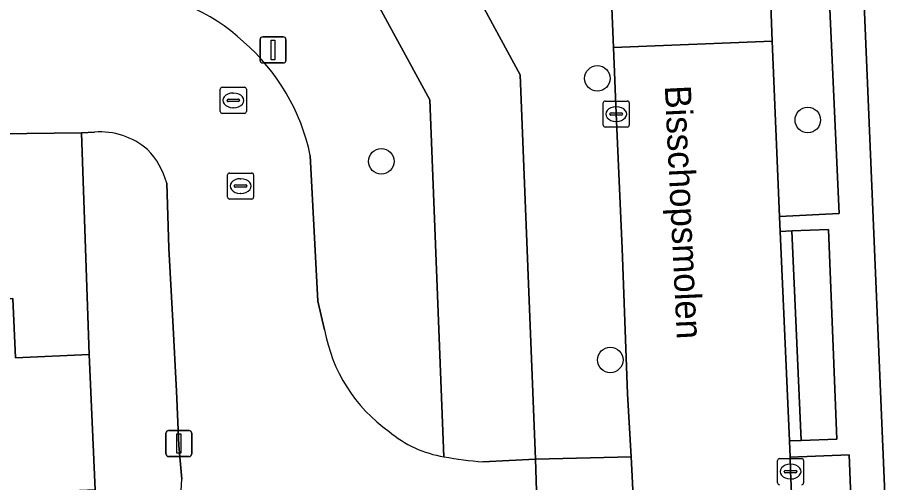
# Model space of a CAD drawing. Extents: x 161241 to 161758, y 384138 to 384885.
# Drawn here: x 161352.12 to 161385.2, y 384187.73 to 384205.58 of the extents above; entities that cross this region are included whole.
import ezdxf

# ---------------------------------------------------------------- set-up
doc = ezdxf.new("R2010")
doc.units = 0
for name, color, linetype in [('IMGEO_Boom', 7, 'Continuous'), ('IMGEO_Erf', 7, 'Continuous'), ('IMGEO_Groenvoorziening', 7, 'Continuous'), ('IMGEO_Kolk', 7, 'Continuous'), ('IMGEO_Lichtmast', 7, 'Continuous'), ('IMGEO_Openbare_ruimte_label', 7, 'Continuous'), ('IMGEO_Pand', 7, 'Continuous'), ('IMGEO_Rijbaan_lokaal_open', 7, 'Continuous'), ('IMGEO_Rioolput', 7, 'Continuous'), ('IMGEO_Voetpad_gesloten', 7, 'Continuous'), ('IMGEO_Voetpad_open', 7, 'Continuous')]:
    doc.layers.add(name, color=color, linetype=linetype)

msp = doc.modelspace()

# ---------------------------------------------------------------- linework, layer by layer
at = {"layer": 'IMGEO_Boom'}
for centre in [(161374.372, 384203.236), (161382.441, 384201.639), (161366.084, 384200.055), (161374.867, 384192.441)]:
    msp.add_circle(centre, 0.489, dxfattribs=at)
at = {"layer": 'IMGEO_Erf'}
for points in [[(161403.222, 384286.46), (161382.629, 384295.041), (161382.268, 384292.057), (161381.629, 384276.193), (161381.889, 384271.203), (161384.168, 384216.383), (161385.58, 384183.057), (161393.06, 384183.551), (161393.229, 384179.87), (161399.67, 384180.152), (161399.739, 384178.529), (161407.43, 384178.871), (161407.337, 384183.973), (161408.1, 384184.171), (161414.411, 384183.984), (161416.602, 384194.481), (161414.471, 384194.926), (161415.583, 384200.253), (161414.588, 384200.438), (161414.333, 384206.87)], [(161354.591, 384201.143), (161334.694, 384200.909), (161329.416, 384200.768), (161329.121, 384207.854), (161328.33, 384226.87), (161331.708, 384226.956), (161331.483, 384232.641), (161332.229, 384232.66), (161332.238, 384232.98), (161332.074, 384232.979), (161331.97, 384235.447), (161332.105, 384235.442), (161332.113, 384235.728), (161331.409, 384235.703), (161330.784, 384250)], [(161320.36, 384192.186), (161329.341, 384192.58), (161329.282, 384193.919), (161330.996, 384193.995), (161331.081, 384192.05), (161335.919, 384192.262), (161335.837, 384194.134), (161340.012, 384194.319), (161341.751, 384194.396), (161341.809, 384193.069), (161350.862, 384193.467), (161350.806, 384194.75), (161351.948, 384194.8), (161352.047, 384192.529), (161354.879, 384192.653), (161354.591, 384201.143)]]:
    msp.add_lwpolyline(points, dxfattribs=at)
at = {"layer": 'IMGEO_Groenvoorziening'}
for points in [[(161382.4, 384217.089), (161381.026, 384217.028), (161380.576, 384217.009), (161380.876, 384209.619), (161380.967, 384207.431), (161381.081, 384204.664), (161381.36, 384197.944), (161383.651, 384198.05), (161382.773, 384217.109)], [(161381.763, 384188.721), (161381.764, 384188.689), (161381.781, 384188.161), (161381.942, 384184.532), (161384.192, 384184.618), (161384.031, 384188.808)]]:
    msp.add_lwpolyline(points, close=True, dxfattribs=at)
for points in [[(161369.982, 384188.536), (161371.994, 384188.635), (161371.416, 384203.375), (161369.294, 384207.268), (161367.785, 384207.214), (161365.393, 384207.112), (161367.951, 384202.419), (161368.488, 384188.73)], [(161368.488, 384188.73), (161367.951, 384202.419), (161365.393, 384207.112), (161359.441, 384206.859), (161352.693, 384206.382), (161354.382, 384206.439), (161356.182, 384206.499)], [(161355.082, 384201.175), (161354.591, 384201.143), (161354.879, 384192.653), (161355.107, 384187.458), (161354.21, 384187.419), (161354.395, 384183.249)], [(161363.359, 384200.278), (161363.655, 384194.693), (161363.909, 384193.599)], [(161358.432, 384187.872), (161358.312, 384189.164), (161358.233, 384191.246), (161358.094, 384193.928), (161357.935, 384196.731), (161357.852, 384199.222)]]:
    msp.add_lwpolyline(points, dxfattribs=at)
for centre, radius, start, end in [((161356.158, 384199.791), 6.709, 46.2683, 89.7909), ((161355.659, 384198.684), 7.863, 11.698, 49.2193), ((161355.299, 384198.424), 2.759, 48.9134, 94.5048), ((161355.141, 384198.511), 2.803, 14.6843, 45.3048), ((161369.906, 384194.668), 6.092, 190.1105, 234.632), ((161369.169, 384192.983), 4.307, 229.6373, 260.8986), ((161371.147, 384203.354), 14.864, 259.6965, 265.5063), ((161353.715, 384187.917), 4.717, 278.2883, 359.454)]:
    msp.add_arc(centre, radius, start, end, dxfattribs=at)
at = {"layer": 'IMGEO_Kolk'}
for p, q in [((161374.593, 384201.44), (161374.593, 384202.292)), ((161374.668, 384202.366), (161375.52, 384202.366)), ((161375.594, 384202.292), (161375.594, 384201.44)), ((161375.081, 384202.146), (161375.106, 384202.146)), ((161374.852, 384201.86), (161374.852, 384201.872)), ((161375.29, 384201.823), (161374.892, 384201.823)), ((161374.895, 384201.909), (161375.293, 384201.909)), ((161375.336, 384201.872), (161375.336, 384201.86)), ((161375.52, 384201.366), (161374.668, 384201.366)), ((161375.104, 384201.586), (161375.079, 384201.586)), ((161360.186, 384198.682), (161360.186, 384199.534)), ((161360.261, 384199.608), (161361.113, 384199.608)), ((161360.674, 384199.388), (161360.699, 384199.388)), ((161361.187, 384199.534), (161361.187, 384198.682)), ((161360.445, 384199.102), (161360.445, 384199.114)), ((161360.883, 384199.065), (161360.485, 384199.065)), ((161360.488, 384199.151), (161360.886, 384199.151)), ((161360.929, 384199.114), (161360.929, 384199.102)), ((161360.697, 384198.828), (161360.672, 384198.828)), ((161361.113, 384198.608), (161360.261, 384198.608)), ((161381.28, 384187.735), (161381.28, 384188.587)), ((161381.355, 384188.661), (161382.207, 384188.661)), ((161381.768, 384188.441), (161381.793, 384188.441)), ((161382.281, 384188.587), (161382.281, 384187.735)), ((161381.539, 384188.155), (161381.539, 384188.167)), ((161381.977, 384188.118), (161381.579, 384188.118)), ((161381.582, 384188.204), (161381.98, 384188.204)), ((161382.023, 384188.167), (161382.023, 384188.155)), ((161381.791, 384187.881), (161381.766, 384187.881))]:
    msp.add_line(p, q, dxfattribs=at)
for points in [[(161374.593, 384201.44), (161374.593, 384202.292)], [(161374.668, 384202.366), (161375.52, 384202.366)], [(161375.594, 384202.292), (161375.594, 384201.44)], [(161375.52, 384201.366), (161374.668, 384201.366)], [(161360.186, 384198.682), (161360.186, 384199.534)], [(161360.261, 384199.608), (161361.113, 384199.608)], [(161361.187, 384199.534), (161361.187, 384198.682)], [(161361.113, 384198.608), (161360.261, 384198.608)], [(161381.28, 384187.735), (161381.28, 384188.587)], [(161381.355, 384188.661), (161382.207, 384188.661)], [(161382.281, 384188.587), (161382.281, 384187.735)]]:
    msp.add_lwpolyline(points, dxfattribs=at)
for centre, radius, start, end in [((161374.67, 384202.29), 0.0765, 91.552, 178.448), ((161374.67, 384202.29), 0.0765, 91.552, 178.448), ((161375.518, 384202.29), 0.0765, 1.552, 88.448), ((161375.518, 384202.29), 0.0765, 1.552, 88.448), ((161374.892, 384201.869), 0.0403, 85.8775, 175.7526), ((161374.889, 384201.859), 0.0366, 178.938, 274.7102), ((161375.293, 384201.866), 0.043, 264.8664, 352.4533), ((161375.297, 384201.871), 0.0386, 1.7309, 96.639), ((161374.67, 384201.442), 0.0765, 181.552, 268.448), ((161374.67, 384201.442), 0.0765, 181.552, 268.448), ((161375.518, 384201.442), 0.0765, 271.552, 358.448), ((161375.518, 384201.442), 0.0765, 271.552, 358.448), ((161360.263, 384199.532), 0.0765, 91.552, 178.448), ((161360.263, 384199.532), 0.0765, 91.552, 178.448), ((161361.111, 384199.532), 0.0765, 1.552, 88.448), ((161361.111, 384199.532), 0.0765, 1.552, 88.448), ((161360.485, 384199.111), 0.0403, 85.8775, 175.7526), ((161360.482, 384199.101), 0.0366, 178.938, 274.7102), ((161360.886, 384199.108), 0.043, 264.8664, 352.4533), ((161360.89, 384199.113), 0.0386, 1.7309, 96.639), ((161360.263, 384198.684), 0.0765, 181.552, 268.448), ((161360.263, 384198.684), 0.0765, 181.552, 268.448), ((161361.111, 384198.684), 0.0765, 271.552, 358.448), ((161361.111, 384198.684), 0.0765, 271.552, 358.448), ((161381.357, 384188.585), 0.0765, 91.552, 178.448), ((161381.357, 384188.585), 0.0765, 91.552, 178.448), ((161382.205, 384188.585), 0.0765, 1.552, 88.448), ((161382.205, 384188.585), 0.0765, 1.552, 88.448), ((161381.579, 384188.164), 0.0403, 85.8775, 175.7526), ((161381.576, 384188.154), 0.0366, 178.938, 274.7102), ((161381.98, 384188.161), 0.043, 264.8664, 352.4533), ((161381.984, 384188.166), 0.0386, 1.7309, 96.639), ((161381.357, 384187.737), 0.0765, 181.552, 268.448), ((161381.357, 384187.737), 0.0765, 181.552, 268.448), ((161382.205, 384187.737), 0.0765, 271.552, 358.448), ((161382.205, 384187.737), 0.0765, 271.552, 358.448)]:
    msp.add_arc(centre, radius, start, end, dxfattribs=at)
for centre, major_axis, ratio, start_param, end_param in [((161375.08, 384201.866), (-0.387, 0.002), 0.722429, 4.712389, 7.853982), ((161375.105, 384201.866), (-0.39, 0.002), 0.717154, 1.570796, 4.712389), ((161360.673, 384199.108), (-0.387, 0.002), 0.722429, 4.712389, 7.853982), ((161360.698, 384199.108), (-0.39, 0.002), 0.717154, 1.570796, 4.712389), ((161381.767, 384188.161), (-0.387, 0.002), 0.722429, 4.712389, 7.853982), ((161381.792, 384188.161), (-0.39, 0.002), 0.717154, 1.570796, 4.712389)]:
    msp.add_ellipse(centre, major_axis=major_axis, ratio=ratio, start_param=start_param, end_param=end_param, dxfattribs=at)
at = {"layer": 'IMGEO_Lichtmast'}
for p, q in [((161361.435, 384203.926), (161361.435, 384204.726)), ((161361.435, 384204.726), (161361.435, 384203.926)), ((161361.535, 384204.826), (161362.325, 384204.826)), ((161362.325, 384204.826), (161361.535, 384204.826)), ((161362.425, 384204.726), (161362.425, 384203.926)), ((161362.425, 384203.926), (161362.425, 384204.726)), ((161362.325, 384203.826), (161361.535, 384203.826)), ((161361.535, 384203.826), (161362.325, 384203.826)), ((161357.922, 384189.738), (161358.712, 384189.738)), ((161358.712, 384189.738), (161357.922, 384189.738)), ((161357.822, 384188.838), (161357.822, 384189.638)), ((161357.822, 384189.638), (161357.822, 384188.838)), ((161358.812, 384189.638), (161358.812, 384188.838)), ((161358.812, 384188.838), (161358.812, 384189.638)), ((161358.712, 384188.738), (161357.922, 384188.738)), ((161357.922, 384188.738), (161358.712, 384188.738))]:
    msp.add_line(p, q, dxfattribs=at)
for points in [[(161361.855, 384204.701), (161362.005, 384204.701), (161362.005, 384203.951), (161361.855, 384203.951), (161361.855, 384204.701)], [(161358.242, 384189.613), (161358.392, 384189.613), (161358.392, 384188.863), (161358.242, 384188.863), (161358.242, 384189.613)]]:
    msp.add_lwpolyline(points, dxfattribs=at)
for centre, start, end in [((161361.535, 384204.726), 90, 180), ((161361.535, 384204.726), 90, 180), ((161362.325, 384204.726), 0, 90), ((161362.325, 384204.726), 360, 90), ((161361.535, 384203.926), 180, 270), ((161361.535, 384203.926), 180, 270), ((161362.325, 384203.926), 270, 0), ((161362.325, 384203.926), 270, 0), ((161357.922, 384189.638), 90, 180), ((161357.922, 384189.638), 90, 180), ((161358.712, 384189.638), 0, 90), ((161358.712, 384189.638), 360, 90), ((161357.922, 384188.838), 180, 270), ((161357.922, 384188.838), 180, 270), ((161358.712, 384188.838), 270, 0), ((161358.712, 384188.838), 270, 0)]:
    msp.add_arc(centre, 0.1, start, end, dxfattribs=at)
at = {"layer": 'IMGEO_Pand'}
msp.add_lwpolyline([(161355.107, 384187.458), (161354.879, 384192.653), (161352.047, 384192.529), (161351.948, 384194.8), (161350.806, 384194.75), (161350.862, 384193.467), (161341.809, 384193.069), (161341.751, 384194.396), (161340.012, 384194.319), (161335.837, 384194.134), (161335.919, 384192.262), (161331.081, 384192.05), (161330.996, 384193.995), (161329.282, 384193.919), (161329.341, 384192.58), (161320.36, 384192.186)], dxfattribs=at)
at = {"layer": 'IMGEO_Rijbaan_lokaal_open'}
for points in [[(161333.147, 384242.867), (161333.411, 384236.512), (161333.617, 384232.219), (161333.763, 384228.005), (161333.973, 384222.651), (161334.206, 384217.517), (161334.413, 384211.983), (161334.554, 384209.391), (161334.636, 384206.829), (161334.479, 384206.784), (161334.694, 384200.909), (161354.591, 384201.143), (161355.082, 384201.175)], [(161381.763, 384188.721), (161381.743, 384189.339), (161381.384, 384197.371), (161381.361, 384197.918), (161381.36, 384197.944), (161381.081, 384204.664), (161374.991, 384204.418), (161375.095, 384201.888), (161375.327, 384196.714), (161375.533, 384191.14), (161375.666, 384188.725), (161375.721, 384187.727), (161375.885, 384183.818), (161376.129, 384176.971), (161376.338, 384172.316), (161382.393, 384172.574), (161382.333, 384174.169), (161382.282, 384175.528)], [(161363.909, 384193.599), (161363.655, 384194.693), (161363.359, 384200.278)], [(161357.852, 384199.222), (161357.935, 384196.731), (161358.094, 384193.928), (161358.233, 384191.246), (161358.312, 384189.164), (161358.432, 384187.872)], [(161381.99, 384183.445), (161381.944, 384184.482), (161381.942, 384184.532), (161381.781, 384188.161), (161381.764, 384188.689), (161381.763, 384188.721)], [(161366.546, 384183.478), (161368.659, 384183.589), (161372.154, 384183.772), (161371.994, 384188.635), (161369.982, 384188.536)]]:
    msp.add_lwpolyline(points, dxfattribs=at)
msp.add_lwpolyline([(161380.967, 384207.431), (161374.877, 384207.185), (161374.991, 384204.418), (161381.081, 384204.664)], close=True, dxfattribs=at)
for centre, radius, start, end in [((161356.158, 384199.791), 6.709, 46.2683, 89.7909), ((161355.659, 384198.684), 7.863, 11.698, 49.2193), ((161355.299, 384198.424), 2.759, 48.9134, 94.5048), ((161355.141, 384198.511), 2.803, 14.6843, 45.3048), ((161369.906, 384194.668), 6.092, 190.1105, 234.632), ((161369.169, 384192.983), 4.307, 229.6373, 260.8986), ((161371.147, 384203.354), 14.864, 259.6965, 265.5063), ((161353.715, 384187.917), 4.717, 278.2883, 359.454)]:
    msp.add_arc(centre, radius, start, end, dxfattribs=at)
at = {"layer": 'IMGEO_Rioolput'}
for p, q in [((161359.907, 384201.966), (161359.907, 384202.818)), ((161359.982, 384202.892), (161360.834, 384202.892)), ((161360.395, 384202.672), (161360.42, 384202.672)), ((161360.908, 384202.818), (161360.908, 384201.966)), ((161360.166, 384202.386), (161360.166, 384202.398)), ((161360.604, 384202.349), (161360.206, 384202.349)), ((161360.209, 384202.435), (161360.607, 384202.435)), ((161360.65, 384202.398), (161360.65, 384202.386)), ((161360.418, 384202.112), (161360.393, 384202.112)), ((161360.834, 384201.892), (161359.982, 384201.892))]:
    msp.add_line(p, q, dxfattribs=at)
for points in [[(161359.907, 384201.966), (161359.907, 384202.818)], [(161359.982, 384202.892), (161360.834, 384202.892)], [(161360.908, 384202.818), (161360.908, 384201.966)], [(161360.834, 384201.892), (161359.982, 384201.892)]]:
    msp.add_lwpolyline(points, dxfattribs=at)
for centre, radius, start, end in [((161359.984, 384202.816), 0.0765, 91.552, 178.448), ((161359.984, 384202.816), 0.0765, 91.552, 178.448), ((161360.832, 384202.816), 0.0765, 1.552, 88.448), ((161360.832, 384202.816), 0.0765, 1.552, 88.448), ((161360.206, 384202.395), 0.0403, 85.8775, 175.7526), ((161360.203, 384202.385), 0.0366, 178.938, 274.7102), ((161360.607, 384202.392), 0.043, 264.8664, 352.4533), ((161360.611, 384202.397), 0.0386, 1.7309, 96.639), ((161359.984, 384201.968), 0.0765, 181.552, 268.448), ((161359.984, 384201.968), 0.0765, 181.552, 268.448), ((161360.832, 384201.968), 0.0765, 271.552, 358.448), ((161360.832, 384201.968), 0.0765, 271.552, 358.448)]:
    msp.add_arc(centre, radius, start, end, dxfattribs=at)
for centre, major_axis, ratio, start_param, end_param in [((161360.394, 384202.392), (-0.387, 0.002), 0.722429, 4.712389, 7.853982), ((161360.419, 384202.392), (-0.39, 0.002), 0.717154, 1.570796, 4.712389)]:
    msp.add_ellipse(centre, major_axis=major_axis, ratio=ratio, start_param=start_param, end_param=end_param, dxfattribs=at)
at = {"layer": 'IMGEO_Voetpad_gesloten'}
for points in [[(161381.834, 384197.387), (161381.384, 384197.371), (161381.743, 384189.339), (161382.193, 384189.357)], [(161381.834, 384197.387), (161382.193, 384189.357), (161383.552, 384189.411), (161383.232, 384197.436)]]:
    msp.add_lwpolyline(points, close=True, dxfattribs=at)
at = {"layer": 'IMGEO_Voetpad_open'}
for points in [[(161384.861, 384156.562), (161386.637, 384158.099), (161385.58, 384183.057), (161384.168, 384216.383), (161381.889, 384271.203)], [(161367.806, 384242.815), (161368.033, 384236.668), (161368.125, 384234.509), (161368.228, 384232.07), (161368.506, 384225.862), (161368.6, 384223.663), (161368.701, 384221.283), (161368.949, 384215.194), (161369.05, 384212.817), (161369.146, 384210.568), (161369.294, 384207.268), (161371.416, 384203.375), (161371.994, 384188.635), (161375.666, 384188.725), (161375.533, 384191.14), (161375.327, 384196.714), (161375.095, 384201.888), (161374.991, 384204.418), (161374.877, 384207.185), (161374.869, 384207.368)], [(161381.747, 384242.244), (161382.455, 384226.302), (161382.002, 384226.279), (161382.4, 384217.089), (161382.773, 384217.109), (161383.651, 384198.05), (161381.36, 384197.944), (161381.361, 384197.918), (161381.384, 384197.371), (161381.834, 384197.387), (161383.232, 384197.436), (161383.552, 384189.411), (161382.193, 384189.357), (161381.743, 384189.339), (161381.763, 384188.721), (161384.031, 384188.808), (161384.192, 384184.618), (161381.942, 384184.532), (161381.944, 384184.482), (161381.99, 384183.445)]]:
    msp.add_lwpolyline(points, dxfattribs=at)
msp.add_lwpolyline([(161375.885, 384183.818), (161375.721, 384187.727), (161375.666, 384188.725), (161371.994, 384188.635), (161372.154, 384183.772)], close=True, dxfattribs=at)

# ---------------------------------------------------------------- texts
at = {"layer": 'IMGEO_Openbare_ruimte_label'}
msp.add_text('Bisschopsmolen', height=1, rotation=272.7508, dxfattribs=at).set_placement((161376.955, 384202.947))

doc.saveas('drawing.dxf')
